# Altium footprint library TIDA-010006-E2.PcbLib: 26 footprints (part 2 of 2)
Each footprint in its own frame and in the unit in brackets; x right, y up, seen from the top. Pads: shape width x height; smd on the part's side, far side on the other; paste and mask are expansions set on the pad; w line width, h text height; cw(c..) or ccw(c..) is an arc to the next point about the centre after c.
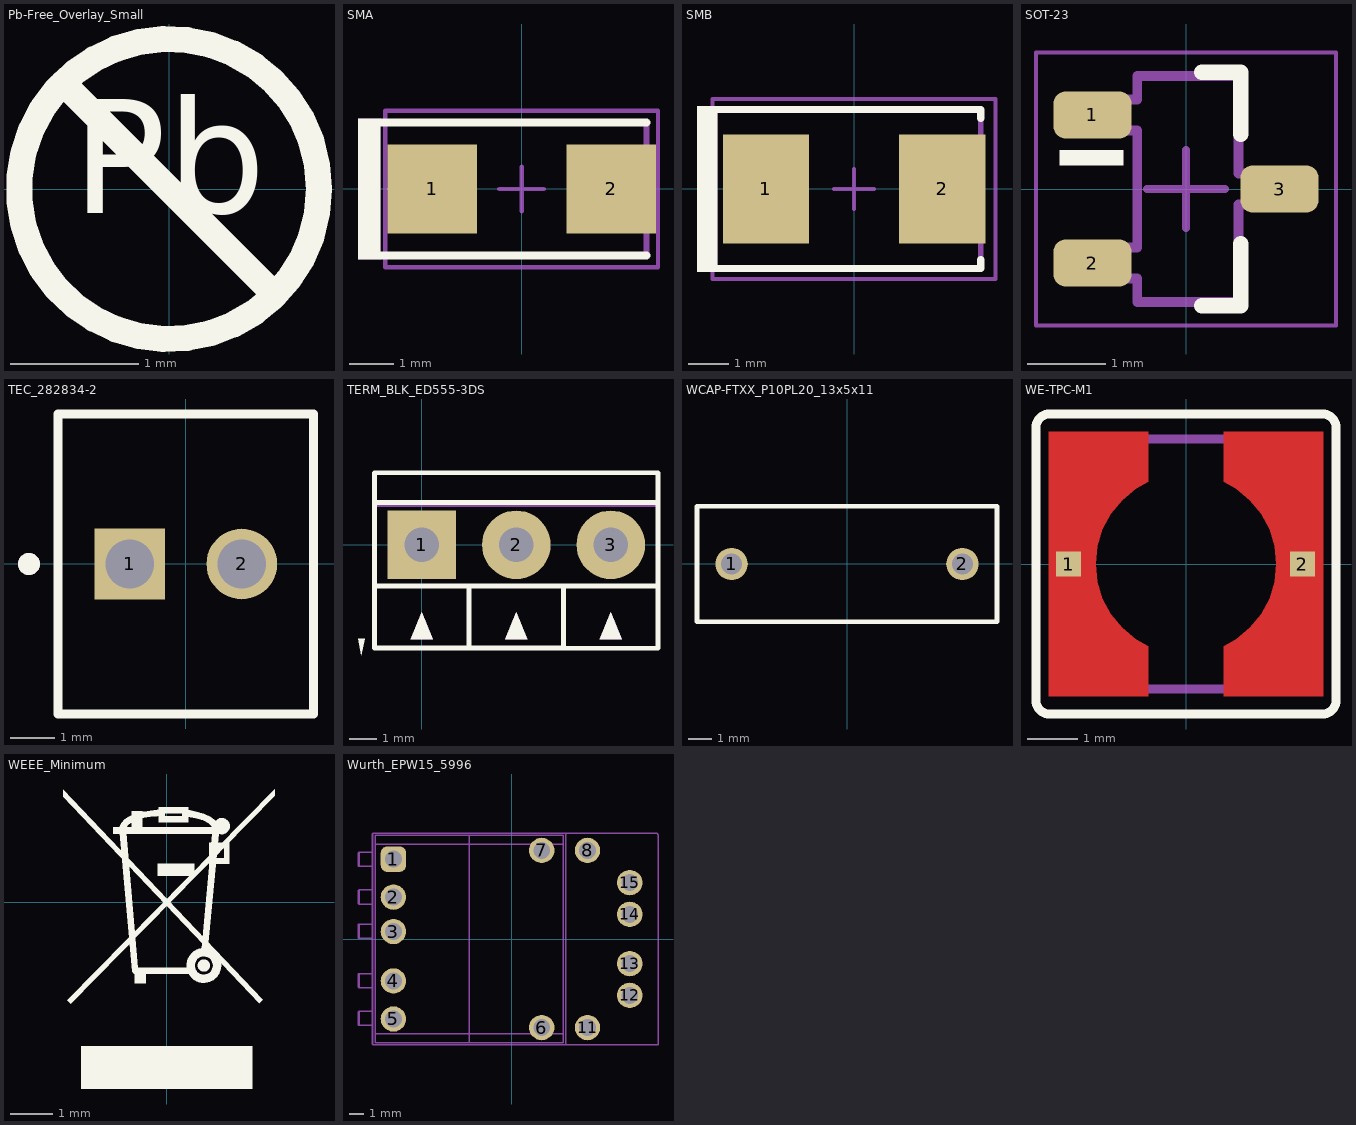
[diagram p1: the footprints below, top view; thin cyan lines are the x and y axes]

## Pb-Free_Overlay_Small [mm]
Top Overlay:
  circle w0.203: c0,0 r1.168
  lines w0.203: -0.826,0.826 0.826,-0.826
  text "Pb" at -0.752,-0.48 h1.52

## SMA [mm] "Molded Diode, 2-Leads, Body 4.3x2.6mm, IPC Medium Density, based on OnSemi component dimensions and land pattern"
height 2.27
pads (2):
  rect 2x2 smd: 1(-2,0) 2(2,0)
Top Overlay:
  rectangle: -3.658,-1.575 -3.15,1.575
  lines w0.178: -3.327,-1.486 2.794,-1.486 ; -3.327,1.486 2.794,1.486
Mechanical 5:
  rectangle: -3.658,-1.575 -3.15,1.575
  lines w0.127: -3.327,-1.486 2.794,-1.486 2.794,1.486 -3.327,1.486
  text ".Designator" at 0.057,0.141 h0.76
Mechanical 15:
  lines w0.1: -0.5,0 0.5,0 ; 0,-0.5 0,0.5 ; -3.05,-1.75 -3.05,1.75 3.05,1.75 3.05,-1.75 -3.05,-1.75
3D body "SMA_nominal.stp": height 2.42, standoff 0.02, extent -2.6,-1.3 2.6,1.3

## SMB [mm] "Molded Diode, 2-Leads, Body 5.4x3.6mm, IPC Medium Density, based on OnSemi component dimensions"
height 2.65
pads (2):
  rect 2.159x2.743 smd: 1(-2.21,0) 2(2.21,0)
Top Overlay:
  rectangle: -3.937,-2.083 -3.429,2.083
  lines w0.178: -3.607,-1.994 3.175,-1.994 3.175,-1.765 ; -3.607,1.994 3.175,1.994 3.175,1.765
Mechanical 5:
  rectangle: -3.937,-2.083 -3.429,2.083
  lines w0.127: -3.607,-1.994 3.175,-1.994 3.175,-1.765 3.175,1.765 3.175,1.994 -3.607,1.994
  text ".Designator" at -1.377,-0.629 h0.76
Mechanical 15:
  lines w0.1: -0.5,0 0.5,0 ; 0,-0.5 0,0.5 ; -3.55,-2.25 3.55,-2.25 3.55,2.25 -3.55,2.25 -3.55,-2.25
3D body "SMB_nominal.stp": height 2.32, standoff 0.02, extent -2.7,-1.8 2.7,1.8

## SOT-23 [mm] "SOT23, 3-Leads, Body 2.9x1.3mm, Pitch 0.95mm, Lead Span 2.5mm, IPC Medium Density"
height 1.1
pads (3):
  rrect50% 1x0.6 smd: 1(-1.2,0.95) 2(-1.2,-0.95) 3(1.2,0)
Top Overlay:
  rectangle: -1.625,0.3 -0.8,0.5
  lines w0.2: 0.2,-1.5 0.7,-1.5 0.7,-0.7 ; 0.2,1.5 0.7,1.5 0.7,0.7
Mechanical 5:
  lines w0.127: -1.16,-1.15 -1.16,-0.75 -0.625,-0.75 -0.625,0.75 -1.16,0.75 -1.16,1.15 -0.625,1.15 -0.625,1.45 0.675,1.45 0.675,0.2 1.21,0.2 1.21,-0.2 0.675,-0.2 0.675,-1.45 -0.625,-1.45 -0.625,-1.15 -1.16,-1.15
  text ".Designator" at 0.356,-0.473 h0.76
Mechanical 15:
  lines w0.05: -1.925,-1.75 1.925,-1.75 1.925,1.75 -1.925,1.75 -1.925,-1.75
  lines w0.1: -0.5,0 0.5,0 ; 0,-0.5 0,0.5
3D body "SW3dPS-sot-3p290x130ll237h100.STEP": height 1, standoff 0, extent -1.16,-1.45 1.21,1.45

## TEC_282834-2 [mm] "TEC"
height 10.3
pads (2):
  rect 1.6x1.6 hole 1.1: 1(-1.27,0)
  round 1.6 hole 1.1: 2(1.27,0)
Top Overlay:
  circle w0.3: c-3.556,0 r0.1
  lines w0.2: -2.895,-3.4 -2.895,3.4 2.895,3.4 2.895,-3.4 -2.895,-3.4
Mechanical 5:
  circle w0.3: c-3.556,0 r0.1
  lines w0.1: -2.895,-3.4 -2.895,3.4 2.895,3.4 2.895,-3.4 -2.895,-3.4
  text ".Designator" at -0.203,-0.559 h0.76
3D body "TEC_282834-2.stp": height 10.01, standoff -3.39, extent -2.77,-3.25 2.77,3.25

## TERM_BLK_ED555-3DS [mm]
height 8.2
pads (3):
  rect 2.54x2.54 hole 1.27: 1(0,0)
  round 2.54 hole 1.27: 2(3.5,0) 3(7,0)
Top Overlay:
  region: -2.235,-4.089 -2.108,-3.48 -2.362,-3.48
  region: 7.4,-3.5 6.6,-3.5 7,-2.5
  region: 3.9,-3.5 3.1,-3.5 3.5,-2.5
  region: 0.4,-3.5 -0.4,-3.5 0,-2.5
  lines w0.178: -1.752,1.572 1.748,1.572 5.248,1.572 8.748,1.572 ; 1.75,-3.815 1.75,-1.528 ; 5.25,-3.815 5.25,-1.528 ; 5.25,-3.81 -1.75,-3.81 -1.75,2.667 5.25,2.667 ; -1.752,-1.528 -1.752,-3.828 1.748,-3.828 5.248,-3.828 8.748,-3.828 8.748,-1.528 ; -1.752,-1.528 1.748,-1.528 5.248,-1.528 8.748,-1.528 ; -1.752,-1.528 -1.752,1.472 -1.752,2.672 1.748,2.672 5.248,2.672 8.748,2.672 8.748,1.472 8.748,-1.528
Mechanical 5:
  region: 0.4,-3.5 -0.4,-3.5 0,-2.5
  region: 3.9,-3.5 3.1,-3.5 3.5,-2.5
  region: 7.4,-3.5 6.6,-3.5 7,-2.5
  lines w0.127: 1.75,-3.815 1.75,-1.528 ; 5.25,-3.815 5.25,-1.528 ; 5.25,-3.81 -1.75,-3.81 -1.75,2.667 5.25,2.667 ; -1.752,-1.528 -1.752,1.472 ; -1.752,-1.528 1.748,-1.528 5.248,-1.528 8.748,-1.528 ; -1.752,-1.528 -1.752,-3.828 1.748,-3.828 5.248,-3.828 8.748,-3.828 8.748,-1.528 ; -1.752,1.472 -1.752,2.672 1.748,2.672 5.248,2.672 8.748,2.672 8.748,1.472 ; -1.752,1.472 1.748,1.472 5.248,1.472 8.748,1.472 ; 8.748,-1.528 8.748,1.472
  text ".Designator" at 4.374,0.388 h0.76
3D body "On-Shore_ED555_3DS.stp": height 8.2, standoff -3.5, extent -1.752,-3.828 8.748,2.672

## WCAP-FTXX_P10PL20_13x5x11 [mm] "TH, 2-Leads, Body 13x5mm, Pitch 10mm"
height 11.5
pads (2):
  round 1.4 hole 0.9: 1(-5,0) 2(5,0)
Top Overlay:
  lines w0.2: -6.5,-2.5 6.5,-2.5 6.5,2.5 -6.5,2.5 -6.5,-2.5
Mechanical 5:
  lines w0.1: -6.5,-2.5 -6.5,2.5 6.5,2.5 6.5,-2.5 -6.5,-2.5
  text ".Designator" at 1.346,0.635 h0.76
3D body "890334023006.stp": height 11, standoff -20, extent -6.5,-2.5 6.5,2.5

## WE-TPC-M1 [mm] "Wurth Elektronik recommended land pattern"
height 2
pads (2):
  rect 0.5x0.5 smd: 1(-2.35,0) 2(2.325,0)
Top Layer:
  region: 0.75,1.64 1.005,1.504 1.279,1.279 1.504,1.005 1.671,0.692 1.774,0.353 1.809,0 1.774,-0.353 1.671,-0.692 1.504,-1.005 1.279,-1.279 1.005,-1.504 0.75,-1.64 0.75,-2.65 2.75,-2.65 2.75,2.65 0.75,2.65
  region: -0.75,1.64 -1.005,1.504 -1.279,1.279 -1.504,1.005 -1.671,0.692 -1.774,0.353 -1.809,0 -1.774,-0.353 -1.671,-0.692 -1.504,-1.005 -1.279,-1.279 -1.005,-1.504 -0.75,-1.64 -0.75,-2.65 -2.75,-2.65 -2.75,2.65 -0.75,2.65
Top Overlay:
  lines w0.178: -2.73,-3 ccw(c-2.73,-3) -2.73,-3 ; -2.73,-3 cw(c-2.73,-2.73) -3,-2.73 -3,-1.73 -3,0 -3,1.73 -3,2.73 cw(c-2.73,2.73) -2.73,3 ; -2.73,-3 -1.73,-3 0,-3 1.73,-3 2.73,-3 ; -2.73,3 ccw(c-2.73,3) -2.73,3 ; -2.73,3 -1.73,3 0,3 1.73,3 2.73,3 ; 2.73,-3 ccw(c2.73,-2.73) 3,-2.73 3,-1.73 3,0 3,1.73 3,2.73 ccw(c2.73,2.73) 2.73,3 ; 2.73,-3 ccw(c2.73,-3) 2.73,-3 ; 2.73,3 ccw(c2.73,3) 2.73,3
Top Paste:
  region: 0.75,1.64 1.005,1.504 1.279,1.279 1.504,1.005 1.671,0.692 1.774,0.353 1.809,0 1.774,-0.353 1.671,-0.692 1.504,-1.005 1.279,-1.279 1.005,-1.504 0.75,-1.64 0.75,-2.65 2.75,-2.65 2.75,2.65 0.75,2.65
  region: -0.75,1.64 -1.005,1.504 -1.279,1.279 -1.504,1.005 -1.671,0.692 -1.774,0.353 -1.809,0 -1.774,-0.353 -1.671,-0.692 -1.504,-1.005 -1.279,-1.279 -1.005,-1.504 -0.75,-1.64 -0.75,-2.65 -2.75,-2.65 -2.75,2.65 -0.75,2.65
Top Solder:
  region: -0.75,1.64 -1.005,1.504 -1.279,1.279 -1.504,1.005 -1.671,0.692 -1.774,0.353 -1.809,0 -1.774,-0.353 -1.671,-0.692 -1.504,-1.005 -1.279,-1.279 -1.005,-1.504 -0.75,-1.64 -0.75,-2.65 -2.75,-2.65 -2.75,2.65 -0.75,2.65
  region: 0.75,1.64 1.005,1.504 1.279,1.279 1.504,1.005 1.671,0.692 1.774,0.353 1.809,0 1.774,-0.353 1.671,-0.692 1.504,-1.005 1.279,-1.279 1.005,-1.504 0.75,-1.64 0.75,-2.65 2.75,-2.65 2.75,2.65 0.75,2.65
Mechanical 5:
  lines w0.102: -2.54,-2.54 2.54,-2.54 2.54,2.54 -2.54,2.54 -2.54,-2.54
  text ".Designator" at -0.66,0.864 h0.76
Mechanical 13:
  lines w0.178: -2.5,-1.23 ccw(c-1.23,-1.23) -1.23,-2.5 1.23,-2.5 ccw(c1.23,-1.23) 2.5,-1.23 2.5,1.23 ccw(c1.23,1.23) 1.23,2.5 -1.23,2.5 ccw(c-1.23,1.23) -2.5,1.23 -2.5,-1.23
3D body: height 2, standoff 0, extent -2.499,-2.499 2.499,2.499

## WEEE_Minimum [mm] "WEEElie bin"
height 2.27
Top Overlay:
  drawing of 23 lines, arcs and shapes, not listed

## Wurth_EPW15_5996 [mm] "TH, 13-Leads, Body 22.1x15.7mm"
height 23.3
pads (13):
  rrect50% 1.8x1.8 hole 1.2: 1(-8.39,5.67)
  round 1.8 hole 1.2: 2(-8.39,2.97) 3(-8.39,0.53) 4(-8.39,-2.98) 5(-8.39,-5.68) 6(2.14,-6.29) 7(2.14,6.29) 8(5.39,6.29) 11(5.39,-6.29) 12(8.39,-4) 13(8.39,-1.75) 14(8.39,1.75) 15(8.39,4)
Mechanical 5:
  circle w0.1: c-8.4,5.7 r0.5
  lines w0.1: -9.905,-6.14 -10.805,-6.14 ; -9.905,-5.14 -10.805,-5.14 ; -9.905,-3.45 -10.805,-3.45 ; -9.905,-2.45 -10.805,-2.45 ; -9.905,0.05 -10.805,0.05 ; -9.905,1.05 -10.805,1.05 ; -9.905,2.48 -10.805,2.48 ; -9.905,3.48 -10.805,3.48 ; -9.905,5.16 -10.805,5.16 ; -9.905,6.16 -10.805,6.16 ; -9.84,-7.494 cw(c-9.805,-7.4) -9.905,-7.4 ; -9.84,-7.4 -9.905,-7.4 ; -9.84,7.4 -9.905,7.4 ; -9.84,7.494 ccw(c-9.805,7.4) -9.905,7.4 ; 3.84,-7.5 10.395,-7.5 10.395,7.4 ccw(c10.295,7.4) 10.295,7.5 3.84,7.5 ; -10.805,-6.14 cw(c-10.805,-6.04) -10.905,-6.04 -10.905,-5.24 cw(c-10.805,-5.24) -10.805,-5.14 ; -10.805,-6.14 -10.805,-5.14 ; -10.805,-3.45 cw(c-10.805,-3.35) -10.905,-3.35 -10.905,-2.55 cw(c-10.805,-2.55) -10.805,-2.45 ; -10.805,-3.45 -10.805,-2.45 ; -10.805,0.05 cw(c-10.805,0.15) -10.905,0.15 -10.905,0.95 cw(c-10.805,0.95) -10.805,1.05 ; -10.805,0.05 -10.805,1.05 ; -10.805,2.48 cw(c-10.805,2.58) -10.905,2.58 -10.905,3.38 cw(c-10.805,3.38) -10.805,3.48 ; -10.805,2.48 -10.805,3.48 ; -10.805,5.16 cw(c-10.805,5.26) -10.905,5.26 -10.905,6.06 cw(c-10.805,6.06) -10.805,6.16 ; -10.805,5.16 -10.805,6.16 ; -9.905,-7.4 -9.905,7.4 ; -9.68,-6.71 -3,-6.71 ; -9.68,-6.71 -9.68,6.71 ; -9.68,-6.71 -9.68,-7.128 -9.68,-7.35 3.68,-7.35 3.68,-7.128 3.68,-6.71 ; -9.68,6.71 -3,6.71 ; -9.68,6.71 -9.68,7.128 -9.68,7.35 3.68,7.35 3.68,7.128 3.68,6.71 ; -3,-6.71 3.68,-6.71 ; -3,-6.71 -3,-7.35 -3,-6.71 ; -3,-6.71 -3,6.71 ; -3,-6.71 -3,6.71 ; -3,6.71 3.68,6.71 ; -3,6.71 -3,7.35 -3,6.71 ; 3.68,-6.71 3.68,6.71 ; -9.84,-7.51 3.84,-7.51 3.84,7.51 -9.84,7.51 -9.84,-7.51
  text ".Designator" at -1.9,-0.4 h0.76
3D body: height 22.6, standoff 22.6, extent -8.899,5.201 -7.901,6.199
3D body "750343910.stp": height 22.6, standoff -3, extent -10.905,-7.5 10.395,7.52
